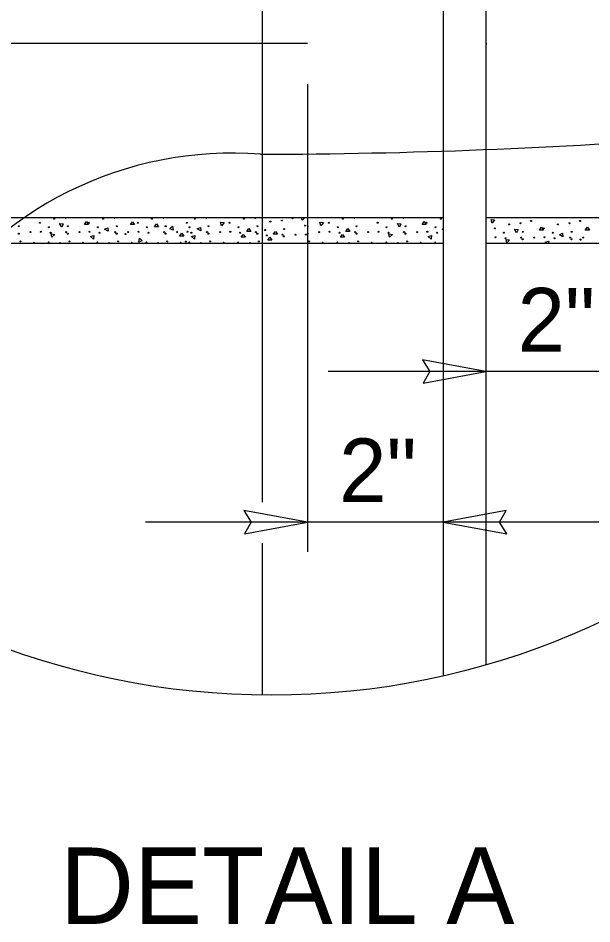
# Model space of a CAD drawing. Extents: x 0 to 2.83, y -0.03 to 1.83.
# Drawn here: x 0.7845 to 0.9019, y 0.1709 to 0.3561 of the extents above; entities that cross this region are included whole.
import ezdxf

# ---------------------------------------------------------------- set-up
doc = ezdxf.new("R2010")
doc.units = 0
for name, color, linetype in [('50', 7, 'Continuous'), ('51', 7, 'Continuous'), ('55', 7, 'Continuous'), ('57', 7, 'Continuous')]:
    doc.layers.add(name, color=color, linetype=linetype)

msp = doc.modelspace()

# ---------------------------------------------------------------- linework, layer by layer
at = {"layer": '50'}
for p, q in [((0.880179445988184, 0.35089625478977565), (0.880379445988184, 0.35089625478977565)), ((0.6903703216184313, 0.3153115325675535), (0.8714627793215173, 0.3153115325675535)), ((0.880179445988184, 0.3153115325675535), (0.9823069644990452, 0.3153115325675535)), ((0.7655600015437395, 0.3101031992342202), (0.8714627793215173, 0.3101031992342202)), ((0.880179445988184, 0.3101031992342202), (0.980048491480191, 0.3101031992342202))]:
    msp.add_line(p, q, dxfattribs=at)
at = {"layer": '51'}
for p, q in [((0.8345007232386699, 0.25710433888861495), (0.8345007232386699, 0.5333983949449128)), ((0.8436961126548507, 0.35089625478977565), (0.680379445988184, 0.35089625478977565)), ((0.8436961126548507, 0.34260451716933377), (0.8436961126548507, 0.24694625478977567)), ((0.8345007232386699, 0.21762933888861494), (0.8345007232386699, 0.24874899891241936))]:
    msp.add_line(p, q, dxfattribs=at)
at = {"layer": '55'}
for p, q in [((0.8714627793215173, 0.5294528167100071), (0.8714627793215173, 0.221579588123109)), ((0.880179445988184, 0.5272006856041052), (0.880179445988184, 0.223829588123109)), ((0.880179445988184, 0.28382125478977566), (0.8479486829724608, 0.28382125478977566)), ((0.9079461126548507, 0.28382125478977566), (0.880179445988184, 0.28382125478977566)), ((0.8436961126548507, 0.253029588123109), (0.8105724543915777, 0.253029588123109)), ((0.8714627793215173, 0.253029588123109), (0.8436961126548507, 0.253029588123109)), ((0.9083794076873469, 0.253029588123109), (0.8714627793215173, 0.253029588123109))]:
    msp.add_line(p, q, dxfattribs=at)
for points in [[(0.8426320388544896, 0.3147768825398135), (0.8424870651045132, 0.3153115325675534)], [(0.8430807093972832, 0.3153115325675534), (0.8426320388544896, 0.3147768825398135)], [(0.793038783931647, 0.31409320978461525), (0.7937658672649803, 0.3140318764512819), (0.7934554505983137, 0.3133714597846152), (0.793038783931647, 0.31409320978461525)], [(0.7981106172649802, 0.3138949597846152), (0.798527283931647, 0.3144938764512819), (0.798944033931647, 0.3138949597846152), (0.7981106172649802, 0.3138949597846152)], [(0.8022031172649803, 0.312932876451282), (0.8028634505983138, 0.31324320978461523), (0.8029248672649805, 0.3125162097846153), (0.8022031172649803, 0.312932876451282)], [(0.8075044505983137, 0.3138758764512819), (0.8079211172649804, 0.3144747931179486), (0.8083378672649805, 0.3138758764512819), (0.8075044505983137, 0.3138758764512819)], [(0.8124302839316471, 0.31340837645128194), (0.8128469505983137, 0.3140072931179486), (0.8132637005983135, 0.31340837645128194), (0.8124302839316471, 0.31340837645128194)], [(0.8162327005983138, 0.3127345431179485), (0.8155705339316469, 0.3130409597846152), (0.8160879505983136, 0.31355529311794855), (0.8162327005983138, 0.3127345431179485)], [(0.8211509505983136, 0.31300187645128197), (0.8218112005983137, 0.3133122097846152), (0.8218727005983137, 0.3125851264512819), (0.8211509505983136, 0.31300187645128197)], [(0.8261379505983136, 0.31365454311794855), (0.8259470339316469, 0.3143587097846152), (0.8266737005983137, 0.31429295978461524), (0.8261379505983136, 0.31365454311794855)], [(0.8464167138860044, 0.31365454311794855), (0.8462257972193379, 0.3143587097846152), (0.8469524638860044, 0.31429295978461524), (0.8464167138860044, 0.31365454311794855)], [(0.862078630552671, 0.31409320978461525), (0.8628057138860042, 0.3140318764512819), (0.8624952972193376, 0.3133714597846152), (0.862078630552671, 0.31409320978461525)], [(0.8671504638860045, 0.3138949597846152), (0.8675671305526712, 0.3144938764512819), (0.867983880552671, 0.3138949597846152), (0.8671504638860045, 0.3138949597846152)], [(0.8814312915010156, 0.31420630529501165), (0.8812403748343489, 0.3149103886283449), (0.8819670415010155, 0.31484472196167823), (0.8814312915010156, 0.31420630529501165)], [(0.8911147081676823, 0.3127538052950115), (0.8915313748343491, 0.3133527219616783), (0.8919481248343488, 0.3127538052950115), (0.8911147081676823, 0.3127538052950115)], [(0.9005085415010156, 0.31273472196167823), (0.9009252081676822, 0.313333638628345), (0.9013419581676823, 0.31273472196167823), (0.9005085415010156, 0.31273472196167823)], [(0.7914331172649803, 0.3112837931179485), (0.7913042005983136, 0.31200187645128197), (0.7920224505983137, 0.3118731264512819), (0.7914331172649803, 0.3112837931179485)], [(0.7993273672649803, 0.31144237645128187), (0.800031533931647, 0.3116332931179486), (0.7999657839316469, 0.3109066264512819), (0.7993273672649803, 0.31144237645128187)], [(0.8175742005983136, 0.3114990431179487), (0.8179908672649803, 0.3120979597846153), (0.8184076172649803, 0.3114990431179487), (0.8175742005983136, 0.3114990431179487)], [(0.8199650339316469, 0.3114316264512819), (0.8206692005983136, 0.3116226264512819), (0.8206034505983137, 0.31089595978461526), (0.8199650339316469, 0.3114316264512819)], [(0.8301694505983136, 0.31128704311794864), (0.8305861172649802, 0.31188595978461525), (0.8310028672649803, 0.31128704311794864), (0.8301694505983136, 0.31128704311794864)], [(0.8312793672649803, 0.31246162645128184), (0.8316960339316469, 0.31306054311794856), (0.832112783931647, 0.31246162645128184), (0.8312793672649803, 0.31246162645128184)], [(0.8356132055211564, 0.3107164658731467), (0.8360298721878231, 0.31131538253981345), (0.836446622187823, 0.3107164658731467), (0.8356132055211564, 0.3107164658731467)], [(0.8367231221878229, 0.31189104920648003), (0.8371397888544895, 0.31248996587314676), (0.8375565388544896, 0.31189104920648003), (0.8367231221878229, 0.31189104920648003)], [(0.8504482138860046, 0.31128704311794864), (0.8508648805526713, 0.31188595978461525), (0.8512816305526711, 0.31128704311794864), (0.8504482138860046, 0.31128704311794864)], [(0.851558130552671, 0.31246162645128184), (0.8519747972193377, 0.31306054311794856), (0.8523915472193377, 0.31246162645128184), (0.851558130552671, 0.31246162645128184)], [(0.8604729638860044, 0.3112837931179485), (0.8603440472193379, 0.31200187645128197), (0.8610622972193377, 0.3118731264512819), (0.8604729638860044, 0.3112837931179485)], [(0.8683672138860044, 0.31144237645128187), (0.869071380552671, 0.3116332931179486), (0.8690056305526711, 0.3109066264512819), (0.8683672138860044, 0.31144237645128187)], [(0.8712429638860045, 0.312932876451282), (0.8714627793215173, 0.313036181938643)], [(0.8714627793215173, 0.3128059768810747), (0.8712429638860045, 0.312932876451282)], [(0.8860428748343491, 0.3129520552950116), (0.8867699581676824, 0.3128907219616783), (0.8864595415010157, 0.31223030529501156), (0.8860428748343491, 0.3129520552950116)], [(0.8952072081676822, 0.3117917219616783), (0.8958675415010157, 0.31210205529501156), (0.8959289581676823, 0.31137505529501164), (0.8952072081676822, 0.3117917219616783)], [(0.8093879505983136, 0.31109845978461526), (0.8099054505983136, 0.3105839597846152), (0.8092431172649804, 0.31027754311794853), (0.8093879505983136, 0.31109845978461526)], [(0.8844372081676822, 0.3101426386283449), (0.8843082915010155, 0.3108607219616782), (0.8850265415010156, 0.31073197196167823), (0.8844372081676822, 0.3101426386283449)], [(0.8923314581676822, 0.3103012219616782), (0.8930356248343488, 0.3104921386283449), (0.8930004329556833, 0.3101031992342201)], [(0.8925674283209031, 0.3101031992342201), (0.8923314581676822, 0.3103012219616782)]]:
    msp.add_lwpolyline(points, dxfattribs=at)
for points in [[(0.880179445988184, 0.28382125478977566), (0.8671961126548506, 0.2861962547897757), (0.8686961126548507, 0.28382125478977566), (0.8673461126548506, 0.28142125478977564)], [(0.8436961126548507, 0.253029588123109), (0.8307127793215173, 0.255404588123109), (0.8322127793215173, 0.253029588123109), (0.8308627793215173, 0.250629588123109)], [(0.8714627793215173, 0.253029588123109), (0.8844627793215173, 0.250654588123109), (0.8829461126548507, 0.253029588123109), (0.8843127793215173, 0.255429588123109)]]:
    msp.add_lwpolyline(points, close=True, dxfattribs=at)
for centre, radius in [((0.8363386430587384, 0.3755134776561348), 0.1578956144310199), ((0.7919066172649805, 0.31507262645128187), 0.00010011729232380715), ((0.8019066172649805, 0.31507262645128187), 0.00010011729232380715), ((0.8119066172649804, 0.31507262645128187), 0.00010011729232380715), ((0.8206677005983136, 0.31507262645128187), 0.00010011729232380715), ((0.8306677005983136, 0.31507262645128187), 0.00010011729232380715), ((0.8406275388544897, 0.3151892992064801), 0.00010011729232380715), ((0.8509464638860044, 0.31507262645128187), 0.00010011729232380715), ((0.8609464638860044, 0.31507262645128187), 0.00010011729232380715), ((0.8709464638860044, 0.31507262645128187), 0.00010011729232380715), ((0.7847144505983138, 0.3135410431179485), 0.00010011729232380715), ((0.7890145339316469, 0.3142479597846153), 0.00010011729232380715), ((0.7908463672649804, 0.3133447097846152), 0.00010011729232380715), ((0.7947144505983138, 0.3135410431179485), 0.00010011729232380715), ((0.7990145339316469, 0.3142479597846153), 0.00010011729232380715), ((0.8008463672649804, 0.3133447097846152), 0.00010011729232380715), ((0.8047144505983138, 0.3135410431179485), 0.00010011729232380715), ((0.8090145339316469, 0.3142479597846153), 0.00010011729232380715), ((0.8108463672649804, 0.3133447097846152), 0.00010011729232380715), ((0.8147144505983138, 0.3135410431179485), 0.00010011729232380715), ((0.8190145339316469, 0.3142479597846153), 0.00010011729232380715), ((0.8196074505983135, 0.3133447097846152), 0.00010011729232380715), ((0.823475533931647, 0.3135410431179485), 0.00010011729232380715), ((0.8277756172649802, 0.3142479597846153), 0.00010011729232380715), ((0.8296074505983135, 0.3133447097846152), 0.00010011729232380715), ((0.833475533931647, 0.3135410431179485), 0.00010011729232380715), ((0.8361114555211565, 0.31450204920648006), 0.00010011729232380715), ((0.8384677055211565, 0.31471804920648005), 0.00010011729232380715), ((0.843219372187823, 0.3136773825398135), 0.00010011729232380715), ((0.8480543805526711, 0.3142479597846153), 0.00010011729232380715), ((0.8498862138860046, 0.3133447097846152), 0.00010011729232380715), ((0.8537542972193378, 0.3135410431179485), 0.00010011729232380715), ((0.8580543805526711, 0.3142479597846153), 0.00010011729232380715), ((0.8598862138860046, 0.3133447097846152), 0.00010011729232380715), ((0.8637542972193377, 0.3135410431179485), 0.00010011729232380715), ((0.8680543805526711, 0.3142479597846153), 0.00010011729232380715), ((0.8698862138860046, 0.3133447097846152), 0.00010011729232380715), ((0.8820186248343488, 0.31310680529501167), 0.00010011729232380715), ((0.8849107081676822, 0.31393147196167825), 0.00010011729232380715), ((0.8872669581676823, 0.31414747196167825), 0.00010011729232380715), ((0.8894267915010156, 0.3146187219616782), 0.00010011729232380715), ((0.8920186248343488, 0.31310680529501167), 0.00010011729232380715), ((0.8949107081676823, 0.31393147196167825), 0.00010011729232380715), ((0.8972669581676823, 0.31414747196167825), 0.00010011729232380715), ((0.8994267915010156, 0.3146187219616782), 0.00010011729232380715), ((0.7846948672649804, 0.3120253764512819), 0.00010011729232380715), ((0.7870707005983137, 0.3123629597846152), 0.00010011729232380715), ((0.7891716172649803, 0.31242187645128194), 0.00010011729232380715), ((0.791199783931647, 0.3122255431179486), 0.00010011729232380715), ((0.794400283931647, 0.3123629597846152), 0.00010011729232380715), ((0.7946948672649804, 0.3120253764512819), 0.00010011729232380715), ((0.7970707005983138, 0.3123629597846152), 0.00010011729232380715), ((0.7991716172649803, 0.31242187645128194), 0.00010011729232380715), ((0.801199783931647, 0.3122255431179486), 0.00010011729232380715), ((0.804400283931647, 0.3123629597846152), 0.00010011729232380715), ((0.8046948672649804, 0.3120253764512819), 0.00010011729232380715), ((0.8065129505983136, 0.31194087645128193), 0.00010011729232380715), ((0.8070707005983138, 0.3123629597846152), 0.00010011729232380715), ((0.8091716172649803, 0.31242187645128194), 0.00010011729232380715), ((0.811199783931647, 0.3122255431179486), 0.00010011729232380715), ((0.814400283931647, 0.3123629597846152), 0.00010011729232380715), ((0.8146948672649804, 0.3120253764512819), 0.00010011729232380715), ((0.8170707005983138, 0.3123629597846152), 0.00010011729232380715), ((0.8191716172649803, 0.31242187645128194), 0.00010011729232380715), ((0.8199608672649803, 0.3122255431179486), 0.00010011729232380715), ((0.8231613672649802, 0.3123629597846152), 0.00010011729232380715), ((0.8234559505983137, 0.3120253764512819), 0.00010011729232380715), ((0.825831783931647, 0.3123629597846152), 0.00010011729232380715), ((0.8279327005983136, 0.31242187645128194), 0.00010011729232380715), ((0.8299608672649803, 0.3122255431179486), 0.00010011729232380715), ((0.8331613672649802, 0.3123629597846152), 0.00010011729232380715), ((0.8334559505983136, 0.3120253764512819), 0.00010011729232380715), ((0.8350512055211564, 0.31277413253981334), 0.00010011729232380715), ((0.8354046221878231, 0.3116549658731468), 0.00010011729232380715), ((0.838605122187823, 0.3117923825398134), 0.00010011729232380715), ((0.8388997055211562, 0.31145479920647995), 0.00010011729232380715), ((0.8389192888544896, 0.31297046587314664), 0.00010011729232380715), ((0.8412755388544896, 0.3117923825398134), 0.00010011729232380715), ((0.8433764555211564, 0.3118512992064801), 0.00010011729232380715), ((0.8461105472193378, 0.3123629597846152), 0.00010011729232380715), ((0.8482114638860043, 0.31242187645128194), 0.00010011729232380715), ((0.850239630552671, 0.3122255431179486), 0.00010011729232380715), ((0.853440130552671, 0.3123629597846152), 0.00010011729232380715), ((0.8537347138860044, 0.3120253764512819), 0.00010011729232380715), ((0.8561105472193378, 0.3123629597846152), 0.00010011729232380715), ((0.8582114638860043, 0.31242187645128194), 0.00010011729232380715), ((0.860239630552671, 0.3122255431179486), 0.00010011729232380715), ((0.863440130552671, 0.3123629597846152), 0.00010011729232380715), ((0.8637347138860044, 0.3120253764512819), 0.00010011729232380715), ((0.8661105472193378, 0.3123629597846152), 0.00010011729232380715), ((0.8682114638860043, 0.31242187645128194), 0.00010011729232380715), ((0.8702396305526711, 0.3122255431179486), 0.00010011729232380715), ((0.8821757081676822, 0.3112807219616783), 0.00010011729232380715), ((0.8838504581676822, 0.31220355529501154), 0.00010011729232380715), ((0.8874043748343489, 0.31122180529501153), 0.00010011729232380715), ((0.8877185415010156, 0.31239988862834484), 0.00010011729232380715), ((0.8900747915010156, 0.31122180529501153), 0.00010011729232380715), ((0.8921757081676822, 0.3112807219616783), 0.00010011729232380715), ((0.8938504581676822, 0.31220355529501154), 0.00010011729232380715), ((0.8974043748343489, 0.31122180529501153), 0.00010011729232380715), ((0.8977185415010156, 0.31239988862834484), 0.00010011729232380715), ((0.9000747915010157, 0.31122180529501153), 0.00010011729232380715), ((0.7850286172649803, 0.3104349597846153), 0.00010011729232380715), ((0.7950286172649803, 0.3104349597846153), 0.00010011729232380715), ((0.8050286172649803, 0.3104349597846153), 0.00010011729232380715), ((0.8150286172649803, 0.3104349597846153), 0.00010011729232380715), ((0.8188159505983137, 0.31040295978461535), 0.00010011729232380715), ((0.8237897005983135, 0.3104349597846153), 0.00010011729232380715), ((0.8337897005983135, 0.3104349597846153), 0.00010011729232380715), ((0.8440684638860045, 0.3104349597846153), 0.00010011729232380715), ((0.8540684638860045, 0.3104349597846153), 0.00010011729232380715), ((0.8640684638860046, 0.3104349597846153), 0.00010011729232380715), ((0.8842038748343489, 0.311084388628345), 0.00010011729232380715), ((0.8876989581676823, 0.31088422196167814), 0.00010011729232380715), ((0.8942038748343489, 0.311084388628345), 0.00010011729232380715), ((0.8976989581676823, 0.31088422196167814), 0.00010011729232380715), ((0.8995170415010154, 0.31079972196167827), 0.00010011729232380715)]:
    msp.add_circle(centre, radius, dxfattribs=at)
for centre, radius, start, end in [((0.8312827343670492, 1.5619356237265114), 1.2336762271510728, 270.1320361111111, 274.35985833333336), ((0.8282933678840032, 0.2534724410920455), 0.07501880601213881, 85.54228055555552, 209.31916666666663), ((0.7942628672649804, 0.31528862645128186), 0.00010011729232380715, 166.77399036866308, 13.226009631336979), ((0.8042628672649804, 0.31528862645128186), 0.00010011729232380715, 166.77399036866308, 13.226009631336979), ((0.8142628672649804, 0.31528862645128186), 0.00010011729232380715, 166.77399036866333, 13.226009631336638), ((0.8230239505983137, 0.31528862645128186), 0.00010011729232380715, 166.77399036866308, 13.226009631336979), ((0.8330239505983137, 0.31528862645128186), 0.00010011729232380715, 166.7739903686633, 13.226009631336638), ((0.8533027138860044, 0.31528862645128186), 0.00010011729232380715, 166.77399036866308, 13.226009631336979), ((0.8633027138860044, 0.31528862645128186), 0.00010011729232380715, 166.77399036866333, 13.226009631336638), ((0.8437542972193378, 0.3135410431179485), 0.00010011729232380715, 234.4675472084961, 125.53245279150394), ((0.8437347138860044, 0.3120253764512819), 0.00010011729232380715, 247.3214849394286, 112.67851506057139), ((0.7877972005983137, 0.31014045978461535), 0.00010011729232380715, 338.1505538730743, 201.84944612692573), ((0.790767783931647, 0.3101797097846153), 0.00010011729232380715, 310.16331469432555, 229.83668530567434), ((0.793163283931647, 0.3101012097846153), 0.00010011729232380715, 1.1386101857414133, 178.8613898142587), ((0.7977972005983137, 0.31014045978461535), 0.00010011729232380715, 338.15055387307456, 201.8494461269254), ((0.800767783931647, 0.3101797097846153), 0.00010011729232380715, 310.16331469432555, 229.83668530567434), ((0.8031632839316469, 0.3101012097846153), 0.00010011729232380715, 1.1386101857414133, 178.8613898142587), ((0.8077972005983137, 0.31014045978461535), 0.00010011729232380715, 338.1505538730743, 201.84944612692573), ((0.8107677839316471, 0.3101797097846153), 0.00010011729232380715, 310.1633146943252, 229.8366853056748), ((0.8131632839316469, 0.3101012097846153), 0.00010011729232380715, 1.1386101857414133, 178.8613898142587), ((0.8177972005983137, 0.31014045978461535), 0.00010011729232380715, 338.1505538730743, 201.84944612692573), ((0.8195288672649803, 0.3101797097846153), 0.00010011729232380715, 310.163314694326, 229.8366853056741), ((0.8219243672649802, 0.3101012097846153), 0.00010011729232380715, 1.1386101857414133, 178.8613898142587), ((0.826558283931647, 0.31014045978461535), 0.00010011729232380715, 338.15055387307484, 201.84944612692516), ((0.8295288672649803, 0.3101797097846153), 0.00010011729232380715, 310.163314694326, 229.8366853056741), ((0.8319243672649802, 0.3101012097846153), 0.00010011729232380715, 1.1386101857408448, 178.86138981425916), ((0.8468370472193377, 0.31014045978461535), 0.00010011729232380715, 338.1505538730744, 201.84944612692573), ((0.8498076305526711, 0.3101797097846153), 0.00010011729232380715, 310.1633146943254, 229.83668530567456), ((0.8522031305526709, 0.3101012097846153), 0.00010011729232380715, 1.1386101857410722, 178.8613898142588), ((0.8568370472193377, 0.31014045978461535), 0.00010011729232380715, 338.1505538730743, 201.84944612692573), ((0.8598076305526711, 0.3101797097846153), 0.00010011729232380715, 310.16331469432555, 229.83668530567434), ((0.862203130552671, 0.3101012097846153), 0.00010011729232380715, 1.1386101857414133, 178.8613898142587), ((0.8668370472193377, 0.31014045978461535), 0.00010011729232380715, 338.1505538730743, 201.84944612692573), ((0.8698076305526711, 0.3101797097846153), 0.00010011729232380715, 310.163314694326, 229.8366853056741)]:
    msp.add_arc(centre, radius, start, end, dxfattribs=at)

# ---------------------------------------------------------------- texts
at = {"layer": '57'}
for s, height, p in [('2"', 0.013016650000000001, (0.8866627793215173, 0.287904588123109)), ('2"', 0.013016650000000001, (0.850179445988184, 0.2571129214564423)), ('DETAIL A', 0.015625, (0.793129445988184, 0.170854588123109))]:
    msp.add_text(s, height=height, dxfattribs=at).set_placement(p)

doc.saveas('drawing.dxf')
